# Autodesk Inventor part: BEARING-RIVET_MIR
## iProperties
Created: 2007-12
Part Number: BEARING-RIVET_MIR
Document SubType Name: Modeling
Density: 1 g/cm^3
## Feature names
1. Derived Body1 [Tagging]
